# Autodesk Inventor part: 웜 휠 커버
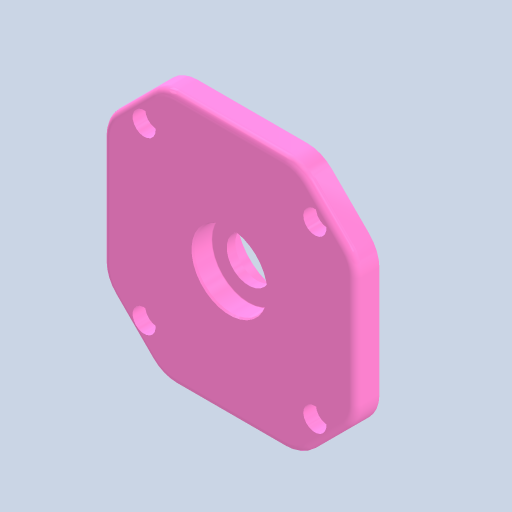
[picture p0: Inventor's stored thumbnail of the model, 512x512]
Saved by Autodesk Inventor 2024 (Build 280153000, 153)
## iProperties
Created: 2026-01
Part Number: 웜 휠 커버
Material: 알루미늄 6061
Document SubType Name: Modeling
Designer: 2-10
Density: 2.7 g/cm^3
Appearance: 기본값
Author: jhkim
Sending System: Autodesk Inventor 2026
Preprocessor: ST-DEVELOPER v20.1
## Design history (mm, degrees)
feature "솔리드1"
node "솔리드2"
